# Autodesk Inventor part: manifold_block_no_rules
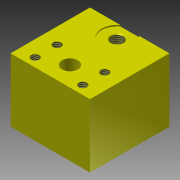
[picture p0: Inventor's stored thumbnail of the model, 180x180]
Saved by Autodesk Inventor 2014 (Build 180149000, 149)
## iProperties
Created: 2006-02
Part Number: manifold_block_no_rules
Document SubType Name: Modeling
Designer: C Bull
Manufacturer: Standard
Standards Organization: Custom
Material: SAE 1020
Mass: 3910.59 g
Surface Area: 647.837 cm^2
Volume: 497.53 cm^3
Density: 7.86 g/cm^3
Appearance: Smooth - Yellow
Author: C Bull
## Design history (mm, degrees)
sketch "Sketch2"
  geometry: L1 (31.75, -31.75)-(-31.75, -31.75); L2 (-31.75, -31.75)-(-31.75, 31.75); L3 (-31.75, 31.75)-(31.75, 31.75); L4 (31.75, 31.75)-(31.75, -31.75); L5 (-19.05, -24.765)-(19.05, -7.239); 7 further points
  constraints: 10 end point, 3 horizontal alignment, 3 midpoint, 3 vertical alignment, 2 parallel, 1 coincident, 1 horizontal, 1 perpendicular
  dimensions: "block_height" = 63.5 distance of L3.end L1.start; "block_width" = 63.5 distance of L1.start L1.end; "port_a_vert_offset" = 47.752 distance from line of point (0, -16.002) L3; "port_a_hor_offset" = 31.75 distance from line of point (0, -16.002) L4; "port_a_x_dist_between_screw" = 38.1 distance of L5.end point (-19.05, -7.239); "port_a_y_dist_between_screw" = 17.526 distance of L5.end point (19.05, -24.765)
extrude "Extrusion1" new body sketch "Sketch2" taper "d8" = 0 deg; distance "block_depth" = 50.8
hole "Port_A" sketch "Sketch2" diameter "port_a_port_dia" = 12.7; stored, may be unused: countersink angle "d13" = 90 deg, drill point angle "port_a_drill_tip_angle" = 118 deg; dims "d10" = 6, "d11" = 4, "d12" = 2, "port_a_d_d" = 25.4 (derived)
hole "Port_A_Threads" sketch "Sketch2" diameter "d16" = 6.4008; stored, may be unused: countersink angle "d20" = 90 deg, drill point angle "d22" = 118 deg; dims "d17" = 6, "d18" = 4, "d19" = 2, "d21" = 14.351 (derived)
sketch "Sketch3"
  geometry: L1 (31.75, -32.832)-(31.75, 30.668) reference; 1 further point
  dimensions: "SAE_Port" = 31.75 distance from line of point (0, 20.668) L1 (= port_a_hor_offset); "d24" = 10 vertical distance of point (0, 20.668) L1.end
feature "iFeature7:1" sketch "Sketch3"
sketch "Sketch4"
  geometry: L1 (63.5, -50.8)-(63.5, 0) reference; L2 (12.7, -34.163)-(50.8, -16.637); 5 further points
  constraints: 2 end point, 2 horizontal alignment, 2 vertical alignment, 1 coincident, 1 midpoint
  dimensions: "port_c_hor_offset" = 31.75 distance from line of point (31.75, -25.4) L1; "port_c_depth_from_front" = 25.4 vertical distance of point (31.75, -25.4) L1.start; "port_c_x_dist_between_screw" = 38.1 distance of point (50.8, -34.163) L2.start; "port_c_y_dist_between_screw" = 17.526 distance of L2.end point (50.8, -34.163)
hole "Port_C" sketch "Sketch4" diameter "port_c_port_dia" = 12.7; stored, may be unused: countersink angle "d33" = 90 deg, drill point angle "port_c_drill_tip_angle" = 118 deg; dims "d30" = 6, "d31" = 4, "d32" = 2, "port_c_vert_offset" = 47.752
hole "Port_C_Threads" sketch "Sketch4" diameter "d36" = 6.4008; stored, may be unused: countersink angle "d40" = 90 deg, drill point angle "d42" = 118 deg; dims "d37" = 6, "d38" = 4, "d39" = 2, "d41" = 14.351 (derived)
sketch "Sketch5"
  geometry: L1 (31.75, 31.75)-(31.75, -31.75) reference; L2 (31.75, -31.75)-(-31.75, -31.75) reference; L3 (19.05, 7.239)-(-19.05, 24.765); 4 further points
  constraints: 2 end point, 2 horizontal alignment, 2 vertical alignment, 1 coincident, 1 midpoint
  dimensions: "port_b_x_dist_between_screw" = 38.1 distance of L3.start point (-19.05, 7.239); "port_b_y_dist_between_screw" = 17.526 distance of point (19.05, 24.765) L3.start; "port_b_vert_offset" = 47.752 distance from line of point (0, 16.002) L2; "port_b_hor_offset" = 31.75 distance from line of L1 point (0, 16.002)
hole "Port_B" sketch "Sketch5" diameter "port_b_port_dia" = 12.7; stored, may be unused: countersink angle "d51" = 82 deg, drill point angle "d53" = 118 deg; dims "d48" = 12.7, "d49" = 9.525, "d50" = 6.35, "port_b_d_d" = 25.4 (= 0.5 x block_depth)
hole "Port_B_Threads" sketch "Sketch5" diameter "d54" = 6.4008; stored, may be unused: countersink angle "d58" = 82 deg, drill point angle "d60" = 118 deg; dims "d55" = 12.7, "d56" = 9.525, "d57" = 6.35, "d59" = 14.351 (derived)
body "Solid1"
other parameters: "tap_dim" = 7.9375 [user parameter], "weight" = 13.83457 [user parameter], "working_press" = 3445000 [user parameter], "AA_SAE_dim" = 23.876 [user parameter], "Port_A_Drill_Depth" = 14.351 [user parameter], "Port_B_Drill_Depth" = 14.351 [user parameter], "Port_C_Drill_Depth" = 14.351 [user parameter]
